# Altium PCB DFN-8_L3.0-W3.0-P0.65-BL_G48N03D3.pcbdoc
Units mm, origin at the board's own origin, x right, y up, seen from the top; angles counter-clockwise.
Board outline 15.76 x 16.56 mm, 2 copper layers (Top Layer, Bottom Layer), stack 0 mm thick; 1 components, 0 nets, 9 pads, 0 vias.
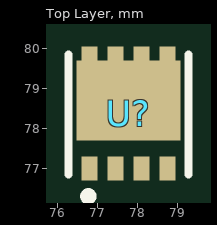
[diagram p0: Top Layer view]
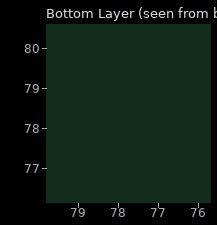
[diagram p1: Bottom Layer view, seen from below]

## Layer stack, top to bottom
Top Layer: signal copper (thickness not stored)
Bottom Layer: signal copper (thickness not stored)

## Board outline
85.61,69.85 69.85,69.85 69.85,86.408 85.61,86.408

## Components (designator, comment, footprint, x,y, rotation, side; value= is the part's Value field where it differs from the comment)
U? "" DFN-8_L3.0-W3.0-P0.65-BL_G48N03D3 77.76,78.38 r0 top

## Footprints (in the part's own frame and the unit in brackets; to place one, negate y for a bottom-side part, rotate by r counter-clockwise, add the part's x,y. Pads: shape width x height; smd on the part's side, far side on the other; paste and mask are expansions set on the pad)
DFN-8_L3.0-W3.0-P0.65-BL_G48N03D3 [mm]
  rect 0.4x0.6 smd paste-100 mask+0.051: 1(-0.975,-1.375) 2(-0.325,-1.375) 3(0.325,-1.375) 4(0.975,-1.375) 5(0.975,1.375) 6(0.325,1.375) 7(-0.325,1.375) 8(-0.975,1.375)
  rect 2.6x2 smd paste-100 mask+0.051: 8(0,0.325)
  silkscreen extent -1.5,-2.18 1.5,1.48

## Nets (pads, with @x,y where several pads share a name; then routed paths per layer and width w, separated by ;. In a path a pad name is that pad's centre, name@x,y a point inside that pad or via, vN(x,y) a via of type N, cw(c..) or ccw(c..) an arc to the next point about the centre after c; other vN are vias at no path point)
pads on no net: U?.1 U?.2 U?.3 U?.4 U?.5 U?.6 U?.7 U?.8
